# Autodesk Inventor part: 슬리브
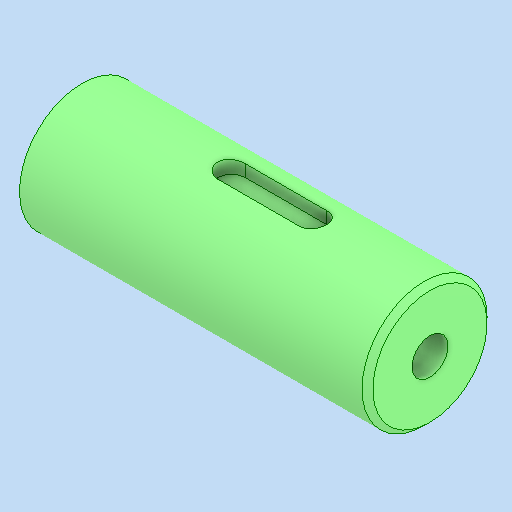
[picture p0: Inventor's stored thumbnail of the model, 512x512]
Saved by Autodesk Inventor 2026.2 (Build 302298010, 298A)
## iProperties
Created: 2026-08
Part Number: 슬리브
Material: 강철, 탄소
Document SubType Name: Modeling
Designer: PC-2-06
Density: 7.87 g/cm^3
Appearance: 기본값
Author: jhkim
Sending System: Autodesk Inventor 2027
Preprocessor: ST-DEVELOPER v20.1
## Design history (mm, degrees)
feature "솔리드1"
node "솔리드2"
